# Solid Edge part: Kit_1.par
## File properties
Sűrűség: 0,000 kg/m^3
Pontosság: 0,990
Author: ahadarics
Last saved by: psaghy
Revision: 77
Username: ahadarics
Dokumentum tartalom típus: 0
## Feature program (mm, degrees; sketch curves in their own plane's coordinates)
base feature "unnamed BaseFeature 1"
sketch for "Furat_1" plane through (0, 0, -111.5) normal (0, 0, -1) x-axis (0, 1, 0)
  hole centre (16.25, 16.25) bore radius 2.4585
hole "Furat_1" nominal diameter 6 finite  VBottomAngle = 118 deg; ThreadDepth = 16 mm
sketch for "unnamed Hole 1" plane through (0, 0, -111.5) normal (0, 0, -1) x-axis (0, 1, 0)
  hole centre (16.25, -16.25) bore radius 2.4585
hole "unnamed Hole 1" finite
sketch for "unnamed Hole 2" plane through (0, 0, -111.5) normal (0, 0, -1) x-axis (0, 1, 0)
  hole centre (-16.25, -16.25) bore radius 2.4585
hole "unnamed Hole 2" finite
sketch for "unnamed Hole 3" plane through (0, 0, -111.5) normal (0, 0, -1) x-axis (0, 1, 0)
  hole centre (-16.25, 16.25) bore radius 2.4585
hole "unnamed Hole 3" finite
pattern "unnamed Pattern 1" of "Furat_1", "unnamed Hole 1", "unnamed Hole 2", "unnamed Hole 3"
sketch for "Furat_5" plane through (23.5, -0.0133, -95.7488) normal (1, 0, 0) x-axis (0, 0, -1)
hole "Furat_5" diameter 9.728 finite  ThreadDepth = 9 mm
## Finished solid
Body 1: solid body, 377 faces, 913 edges, 584 vertices, 1 internal void.
  Faces by surface: plane 138, cylinder 126, cone 35, torus 35, spline 31, sphere 10, swept 2
  Edges by curve: line 330, curve on surface 301, circle 263, spline 18, intersection 1
Bounding box of the edges (mm; curved faces can reach further): 47.001 x 47.000 x 30.500, from (-23.5, -23.5, -115.5) to (23.5005, 23.5, -85).
Cylindrical faces by radius (mm): R0.2287 x1, R0.2297 x1, R0.2305 x1, R0.232 x1, R0.2354 x1, R0.2616 x1, R0.2684 x1, R0.2696 x1, R0.274 x1, R0.2809 x1, R0.2869 x1, R0.2897 x2, R0.2949 x1, R0.2975 x1, R0.2999 x1, R0.3047 x1, R0.3049 x1, R0.3054 x1, R0.3191 x1, R0.3251 x1, R0.3471 x1, R0.361 x1, R0.3789 x1, R0.3925 x1, R0.3994 x1, R0.4078 x1, R0.4206 x1, R0.4339 x1, R0.4364 x1, R0.4536 x1, R0.4559 x1, R0.4564 x1, R0.4771 x1, R0.4781 x1, R0.5 x7, R0.5094 x1, R0.5226 x1, R0.5354 x1, R0.5534 x1, R0.6836 x1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
Conical faces (half-angle, radius in mm at the cone's reference point): 5.1542 deg R0.4847 x1, 27.5528 deg R20.5 x4, 30 deg R4.0866 x1, 45 deg R2.25 x3, 45 deg R2.3 x1, 45 deg R2.4 x1, 45 deg R2.5 x3, 45 deg R3.25 x8, 45 deg R4.85 x8, 45 deg R5.18 x1, 59 deg R2.4585 x4
Toroidal faces (ring radius, tube radius in mm): R0.7228 r0.5 x1, R0.8364 r0.5 x1, R1.4664 r0.5007 x3, R1.6 r0.1 x3, R3.3 r0.3 x4, R3.7 r0.3 x1, R4.95 r0.2 x4, R5.65 r0.5 x4, R7.75 r0.5 x1, R8 r0.5 x1, R14.5 r0.5 x1, R15.5 r0.5 x1, R18 r1 x3, R22.5 r1 x6, R23.8031 r0.5 x1
Spherical faces by radius (mm): R0.5 x4, R1 x6
Planar faces by outward normal: +x 18, +y 8, +z 14, -y 8, -z 30, oblique 60
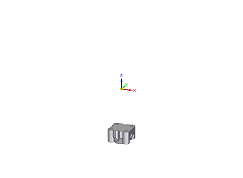
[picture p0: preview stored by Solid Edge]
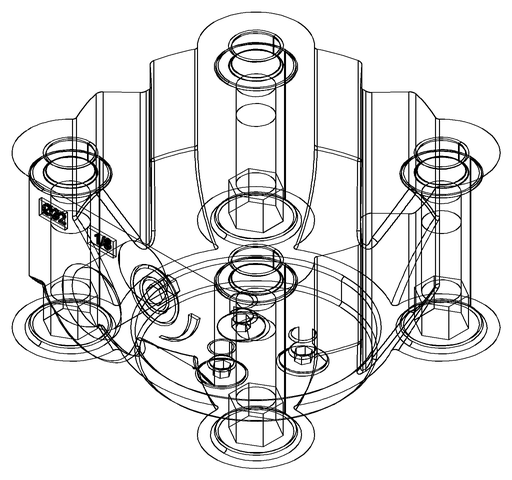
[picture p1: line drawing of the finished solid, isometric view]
